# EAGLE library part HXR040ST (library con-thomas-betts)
THOMAS&BETTS
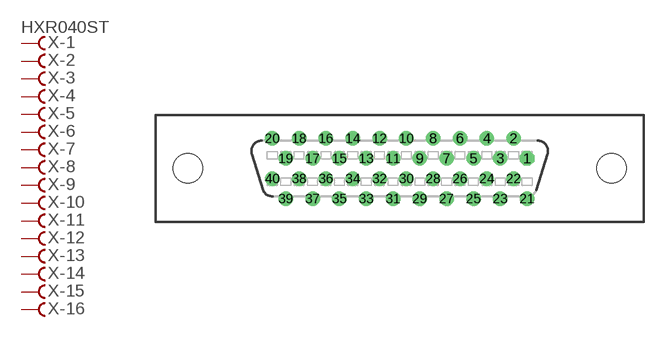
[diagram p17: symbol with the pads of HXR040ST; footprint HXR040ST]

Designator prefix X; gates -1=FV -2=F -3=F -4=F -5=F -6=F -7=F -8=F -9=F -10=F -11=F -12=F -13=F -14=F -15=F -16=F -17=F -18=F -19=F -20=F -21=F -22=F -23=F -24=F -25=F -26=F -27=F -28=F -29=F -30=F -31=F -32=F -33=F -34=F -35=F -36=F -37=F -38=F -39=F -40=F

## HXR040ST (OC_FARNELL: unknown; OC_NEWARK: unknown)  [HXR040ST]
1  -1:F  pas
2  -2:F  pas
3  -3:F  pas
4  -4:F  pas
5  -5:F  pas
6  -6:F  pas
7  -7:F  pas
8  -8:F  pas
9  -9:F  pas
10  -10:F  pas
11  -11:F  pas
12  -12:F  pas
13  -13:F  pas
14  -14:F  pas
15  -15:F  pas
16  -16:F  pas
17  -17:F  pas
18  -18:F  pas
19  -19:F  pas
20  -20:F  pas
21  -21:F  pas
22  -22:F  pas
23  -23:F  pas
24  -24:F  pas
25  -25:F  pas
26  -26:F  pas
27  -27:F  pas
28  -28:F  pas
29  -29:F  pas
30  -30:F  pas
31  -31:F  pas
32  -32:F  pas
33  -33:F  pas
34  -34:F  pas
35  -35:F  pas
36  -36:F  pas
37  -37:F  pas
38  -38:F  pas
39  -39:F  pas
40  -40:F  pas

## Footprint HXR040ST (pad centres in mm)
THOMAS&BETTS HFR040ST29xx, HHR040ST29xx
drill 0.864 octagon: 1 12.065,0.953
drill 0.864 round: 2 10.795,2.857; 3 9.525,0.953; 4 8.255,2.857; 5 6.985,0.953; 6 5.715,2.857; 7 4.445,0.953; 8 3.175,2.857; 9 1.905,0.953; 10 0.635,2.857; 11 -0.635,0.953; 12 -1.905,2.857; 13 -3.175,0.953; 14 -4.445,2.857; 15 -5.715,0.953; 16 -6.985,2.857; 17 -8.255,0.953; 18 -9.525,2.857; 19 -10.795,0.953; 20 -12.065,2.857; 21 12.065,-2.857; 22 10.795,-0.953; 23 9.525,-2.857; 24 8.255,-0.953; 25 6.985,-2.857; 26 5.715,-0.953; 27 4.445,-2.857; 28 3.175,-0.953; 29 1.905,-2.857; 30 0.635,-0.953; 31 -0.635,-2.857; 32 -1.905,-0.953; 33 -3.175,-2.857; 34 -4.445,-0.953; 35 -5.715,-2.857; 36 -6.985,-0.953; 37 -8.255,-2.857; 38 -9.525,-0.953; 39 -10.795,-2.857; 40 -12.065,-0.953
hole 2.769 at 20.066,0.013
hole 2.769 at -20.066,0.013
